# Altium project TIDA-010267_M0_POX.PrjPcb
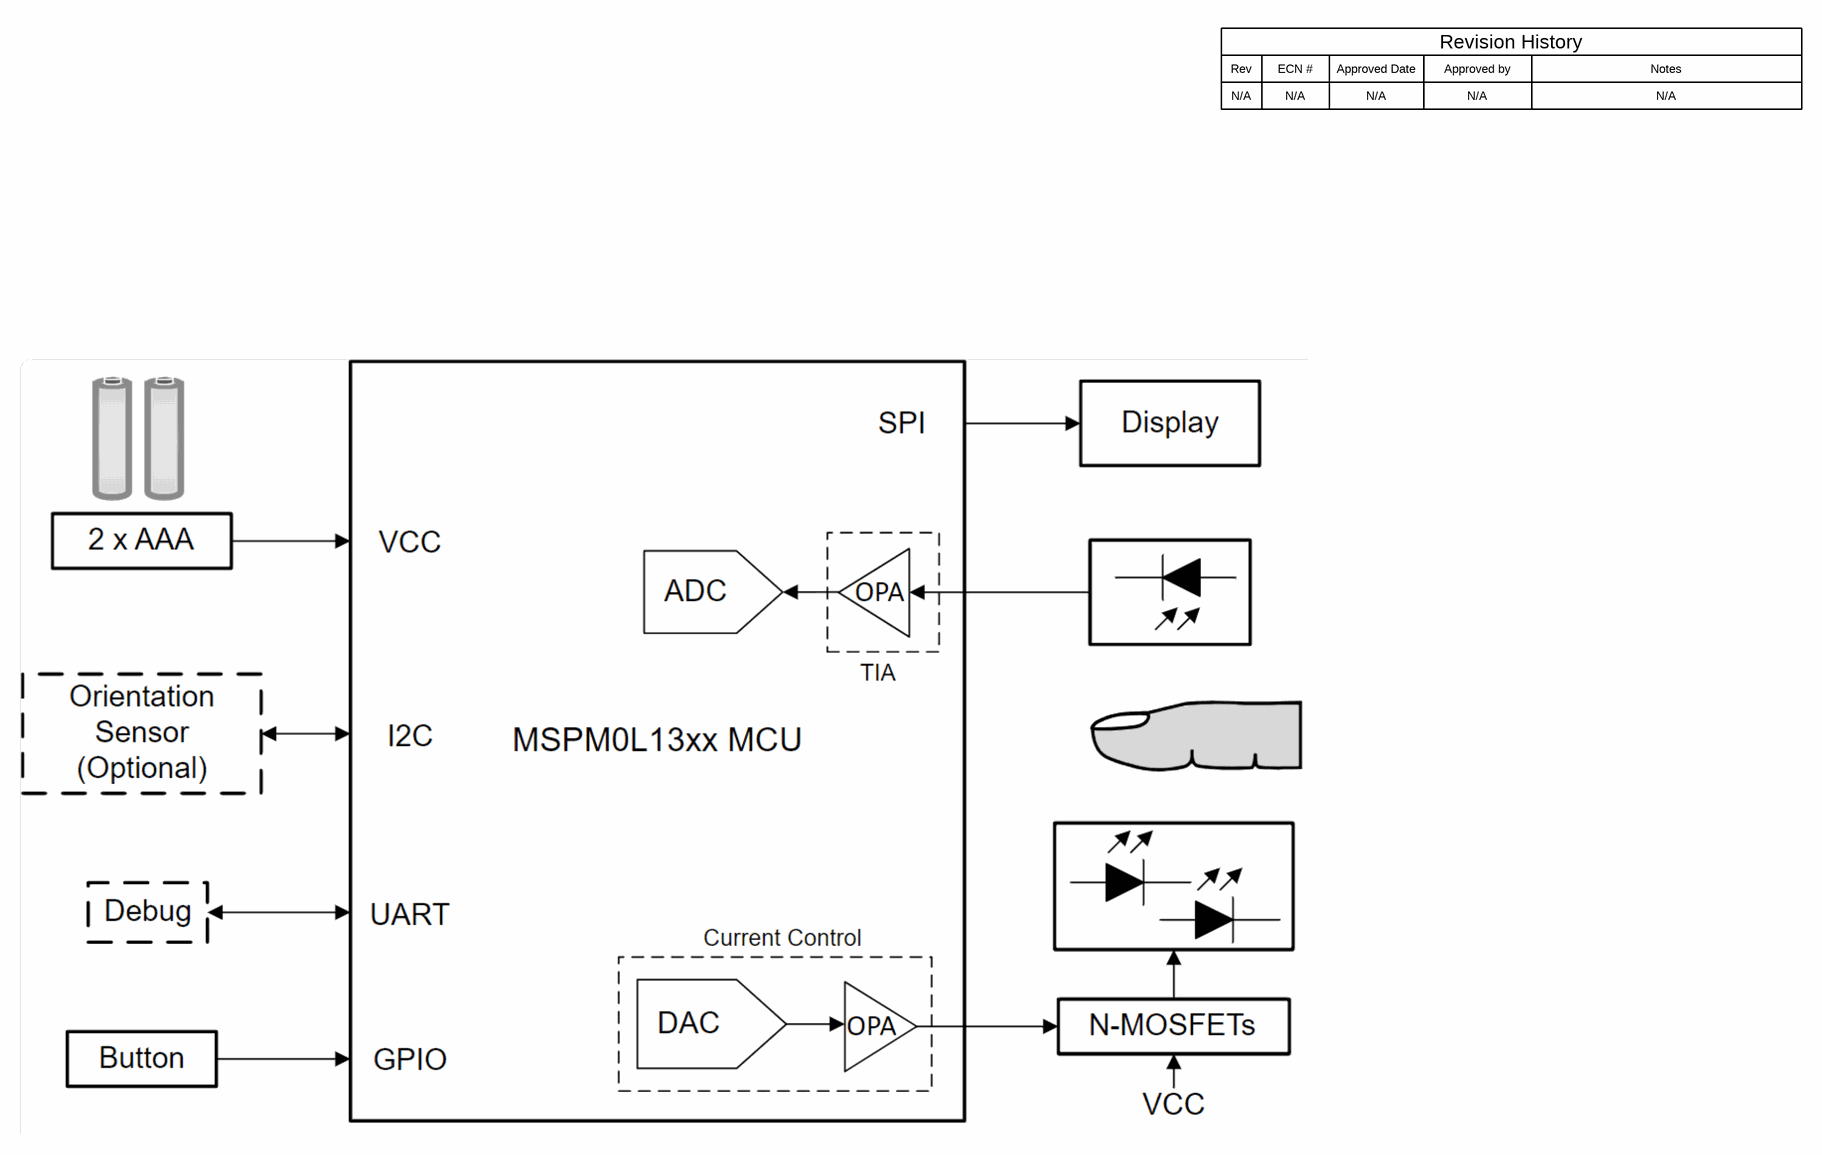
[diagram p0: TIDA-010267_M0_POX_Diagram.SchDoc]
TID: N/A; TechSupport: http://www.ti.com/support; SCH_Rev: A; PRJ_Title: TIDA-010267_M0_POX; PRJ_Number: TIDA-010267_M0_POX; PRJ_Engineer: Rogelio Armino; PRJ_Customer: Public Release; PCB_Rev: A; PCB_Layout: Rogelio Armino; CopyrightYear: 2023
3 sheets, 43 parts. Net scope: global (net labels, ports and power ports of the same name join across sheets).
Board file: TIDA-010267_M0_POX_PCB.PcbDoc
Sheets:
  TIDA-010267_M0_POX_Diagram.SchDoc
  TIDA-010267_M0_POX_Schematic.SchDoc
  TIDA-010267_M0_POX_Hardware.SchDoc

## Sheet TIDA-010267_M0_POX_Diagram.SchDoc
size 431 x 279 mm; Date: Not shown in title block; ApprovedBy: Not shown in title block; CheckedBy: Not shown in title block; Author: Not shown in title block; CompanyName: Not shown in title block; Engineer: Not shown in title block; Organization: Not shown in title block; Address1: Not shown in title block; Address2: Not shown in title block; Address3: Not shown in title block; Address4: Not shown in title block; DocumentNumber: 1; Revision: Use project parameter SCH_Rev; SheetNumber: 1; SheetTotal: 3; PageSetup: Record=PageOptions¦CenterHorizontal=True¦CenterVertical=True¦PrintScale=1.00¦XCorrection=1.00¦YCorrection=1.00¦PrintKind=0¦BorderSize=5000000¦LeftOffset=0¦BottomOffset=0¦Orientation=2¦PaperLength=1000¦PaperWidth=1000¦Scale=100¦PaperSource=15¦PrintQuality=600¦MediaType=1¦DitherType=10¦PaperKind=Letter¦PrintScaleMode=1

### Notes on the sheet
- Rev
- N/A
- ECN #
- Approved Date
- Approved by
- Revision History
- Notes

## Sheet TIDA-010267_M0_POX_Schematic.SchDoc
size 431 x 279 mm; Date: Not shown in title block; ApprovedBy: Not shown in title block; CheckedBy: Not shown in title block; Author: Not shown in title block; CompanyName: Not shown in title block; Engineer: Not shown in title block; Organization: Not shown in title block; Address1: Not shown in title block; Address2: Not shown in title block; Address3: Not shown in title block; Address4: Not shown in title block; DocumentNumber: 2; Revision: Use project parameter SCH_Rev; SheetNumber: 2; SheetTotal: 3; PageSetup: Record=PageOptions¦CenterHorizontal=True¦CenterVertical=True¦PrintScale=1.00¦XCorrection=1.00¦YCorrection=1.00¦PrintKind=0¦BorderSize=5000000¦LeftOffset=0¦BottomOffset=0¦Orientation=2¦PaperLength=1000¦PaperWidth=1000¦Scale=100¦PaperSource=15¦PrintQuality=600¦MediaType=1¦DitherType=10¦PaperKind=Letter¦PrintScaleMode=1
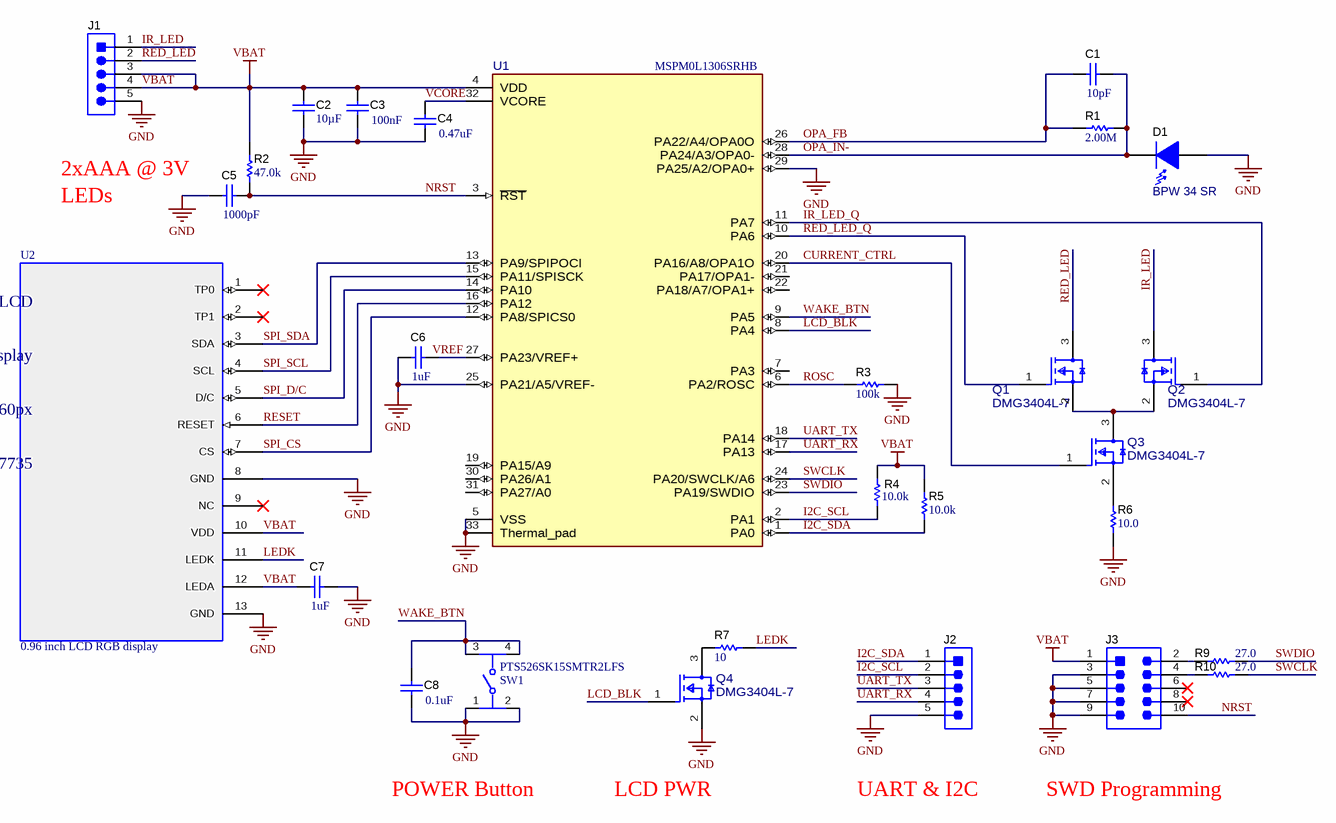
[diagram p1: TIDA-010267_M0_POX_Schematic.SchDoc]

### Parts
C1  ValueDisplayed: 10pF  [0402]  (hidden comment: C0402C100C8GACTU)
C2  ValueDisplayed: 10µF  [0603]  (hidden comment: GRM188R61A106KAALD)
C3  ValueDisplayed: 100nF  [0402]  (hidden comment: GRM155R61A104KA01D)
C4  ValueDisplayed: 0.47uF  [0402]  (hidden comment: GRM155R61A474KE15D)
C5  ValueDisplayed: 1000pF  [0402]  (hidden comment: GRM155R61A102KA01D)
C6  ValueDisplayed: 1uF  [0402]  (hidden comment: GRM155R61E105KA12D)
C7  ValueDisplayed: 1uF  [0402]  (hidden comment: GRM155R61E105KA12D)
C8  ValueDisplayed: 0.1uF  [0402L]  (hidden comment: GRM155R61A104KA01D)
D1  BPW 34 SR  [BPW34SR]
J1  61300511121  [Wurth_61300511121]  (value not drawn)
J2  61300511121  [Wurth_61300511121]  (value not drawn)
J3  FTSH-105-01-L-DV-K  [Samtec_FTSH-105-01-x-DV-K]  (value not drawn)
Q1  DMG3404L-7  [FP-DMG3404L-7_SOT23-MFG]
Q2  DMG3404L-7  [FP-DMG3404L-7_SOT23-MFG]
Q3  DMG3404L-7  [FP-DMG3404L-7_SOT23-MFG]
Q4  DMG3404L-7  [FP-DMG3404L-7_SOT23-MFG]
R1  ValueDisplayed: 2.00M  [0402]  (hidden comment: CRCW04022M00FKED)
R2  ValueDisplayed: 47.0k  [0402]  (hidden comment: RC0402FR-0747KL)
R3  ValueDisplayed: 100k  [0402]  (hidden comment: RG1005P-104-B-T5)
R4  ValueDisplayed: 10.0k  [0402]  (hidden comment: ERJ-2RKF1002X)
R5  ValueDisplayed: 10.0k  [0402]  (hidden comment: ERJ-2RKF1002X)
R6  ValueDisplayed: 10.0  [0603]  (hidden comment: RC0603FR-0710RL)
R7  ValueDisplayed: 10  [0402L]  (hidden comment: CRCW040210R0JNED)
R9  ValueDisplayed: 27.0  [CPF0402]  (hidden comment: CPF0402B27RE1)
R10  ValueDisplayed: 27.0  [CPF0402]  (hidden comment: CPF0402B27RE1)
SW1  PTS526SK15SMTR2LFS  [FP-PTS526SK15SMTR2LFS-MFG]
U1  MSPM0L1306SRHB  [RHB0032N-MFG]
U2  0.96 inch LCD RGB display  [MDT0096A2IS-SPI]

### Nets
GND: C2.2 C3.2 C4.2 C5.2 C6.2 C7.1 C8.2 D1.1(A) J1.5 J2.5 J3.3 J3.5 J3.7 J3.9 Q4.2(S) R3.2 R6.1 SW1.1 SW1.2 U1.5(VSS) U1.25(PA21/A5/VREF-) U1.29(PA25/A2/OPA0+) U1.33(Thermal_pad) U2.8(GND) U2.13(GND)
VBAT: C2.1 C3.1 C7.2 J1.3 J1.4 J3.1 R2.2 R4.2 R5.2 U1.4(VDD) U2.10(VDD) U2.12(LEDA)
CURRENT_CTRL: Q3.1(G) U1.20(PA16/A8/OPA1O)
I2C_SCL: J2.2 R4.1 U1.2(PA1)
I2C_SDA: J2.1 R5.1 U1.1(PA0)
IR_LED: J1.1 Q2.3(D)
IR_LED_Q: Q2.1(G) U1.11(PA7)
LCD_BLK: Q4.1(G) U1.8(PA4)
LEDK: R7.2 U2.11(LEDK)
NRST: C5.1 J3.10 R2.1 U1.3(~{RST})
OPA_FB: C1.2 R1.1 U1.26(PA22/A4/OPA0O)
OPA_IN-: C1.1 D1.2(C) R1.2 U1.28(PA24/A3/OPA0-)
RED_LED: J1.2 Q1.3(D)
RED_LED_Q: Q1.1(G) U1.10(PA6)
RESET: U1.16(PA12) U2.6(RESET)
ROSC: R3.1 U1.6(PA2/ROSC)
SPI_CS: U1.12(PA8/SPICS0) U2.7(CS)
SPI_D/C: U1.14(PA10) U2.5(D/C)
SPI_SCL: U1.15(PA11/SPISCK) U2.4(SCL)
SPI_SDA: U1.13(PA9/SPIPOCI) U2.3(SDA)
SWCLK: R10.2 U1.24(PA20/SWCLK/A6)
SWDIO: R9.2 U1.23(PA19/SWDIO)
UART_RX: J2.4 U1.17(PA13)
UART_TX: J2.3 U1.18(PA14)
VCORE: C4.1 U1.32(VCORE)
WAKE_BTN: C8.1 SW1.3 SW1.4 U1.9(PA5)
NetC6_1: C6.1 U1.27(PA23/VREF+)
NetJ3_2: J3.2 R9.1
NetJ3_4: J3.4 R10.1
NetQ1_2: Q1.2(S) Q2.2(S) Q3.3(D)
NetQ3_2: Q3.2(S) R6.2
NetQ4_3: Q4.3(D) R7.1

Not connected (* = marked no-connect by the designer): J3 6* 8*; U1 7(PA3) 19(PA15/A9) 21(PA17/OPA1-) 22(PA18/A7/OPA1+) 30(PA26/A1) 31(PA27/A0); U2 1(TP0)* 2(TP1)* 9(NC)*

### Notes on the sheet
- 2xAAA @ 3V
- LEDs
- POWER Button
- LCD PWR
- UART & I2C
- SWD Programming
- Labels drawn without touching a wire or pin: VREF

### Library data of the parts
C1 = CMP-0064914-2: CAP, CERM, 10 pF, 10 V,+/- 2.5%, C0G/NP0, 0402; Manufacturer: Kemet; TaMin_C: -55°C; Polarized: N; SizeAreaWB_mm2: 3; Value1: Unknown; U/M: EA; Value: 10pF; TaMax_C: 125°C; SizeZ_mm: 0.6; SizeX_mm: 1; SizeY_mm: 0.5; Value2: 10V; AEC Category: Q200
C2 = CMP-0086193-1: CAP, CERM, 10 µF, 10 V,+/- 10%, X5R, 0603; Manufacturer: MuRata; SizeArea_mm2: 1.28; SizeY_mm: 0.8; TaMax_C: 85°C; TaMin_C: -55°C; Polarized: N; Value2: 10V; SizeAreaWB_mm2: 4.68; SizeZ_mm: 1; SizeX_mm: 1.6; AEC Category: Q200; U/M: EA; Value: 10uF
C3 = CMP-0006562-2: CAP, CERM, 0.1 uF, 10 V, +/- 10%, X5R, 0402; Manufacturer: MuRata; TaMin_C: -55°C; Polarized: N; SizeAreaWB_mm2: 3; Value1: Unknown; U/M: EA; Value: 0.1uF; TaMax_C: 85°C; SizeZ_mm: 0.6; SizeX_mm: 1; SizeY_mm: 0.5; Value2: 10V; AEC Category: Q200
C4 = CMP-0006580-2: CAP, CERM, 0.47 uF, 10 V, +/- 10%, X5R, 0402; Manufacturer: MuRata; TaMin_C: -55°C; Polarized: N; SizeAreaWB_mm2: 3; Value1: Unknown; U/M: EA; Value: 0.47uF; TaMax_C: 85°C; SizeZ_mm: 0.6; SizeX_mm: 1; SizeY_mm: 0.5; Value2: 10V; Cap_F: 470nF; AEC Category: Q200
C5 = CMP-0006560-2: CAP, CERM, 1000 pF, 10 V, +/- 10%, X5R, 0402; Manufacturer: MuRata; TaMin_C: -55°C; Polarized: N; SizeAreaWB_mm2: 3; Value1: Unknown; U/M: EA; Value: 1000pF; TaMax_C: 85°C; SizeZ_mm: 0.6; SizeX_mm: 1; SizeY_mm: 0.5; Value2: 10V; Cap_F: 1nF; AEC Category: Q200
C6 C7 = CMP-0006608-2: CAP, CERM, 1 uF, 25 V, +/- 10%, X5R, 0402; Manufacturer: MuRata; TaMin_C: -55°C; Polarized: N; SizeAreaWB_mm2: 3; Value1: Unknown; U/M: EA; Value: 1uF; TaMax_C: 85°C; SizeZ_mm: 0.6; SizeX_mm: 1; SizeY_mm: 0.5; Value2: 25V; Cap_F: 1µF; AEC Category: Q200
C8 = CMP-0006562-2: CAP, CERM, 0.1 uF, 10 V, +/- 10%, X5R, 0402; Manufacturer: MuRata; TaMin_C: -55°C; Polarized: N; SizeAreaWB_mm2: 3; Value1: Unknown; U/M: EA; Value: 0.1uF; TaMax_C: 85°C; SizeZ_mm: 0.6; SizeX_mm: 1; SizeY_mm: 0.5; Cap_Case: 0402; Value2: 10V; Cap_F: 100nF; AEC Category: Q200
D1 = CMP-0005335-2: PIN Photodiode, SMD; Manufacturer: OSRAM
J1 J2 = CMP-0084909-1: Header, 2.54mm, 5x1, Gold, TH; Manufacturer: Wurth Elektronik; Pitch_mm: 2.54; Gender: Male; Row_Count: 1; Shrouded: N; Current_A: 3A; Voltage_V: 250V
J3 = CMP-0075634-2: Header(Shrouded), 1.27mm, 5x2, Gold, SMT; Manufacturer: Samtec; Pitch_mm: 1.27; Gender: Male; Cert_CSA: Y; Current_A: 3.3A; Row_Count: 2
Q1-Q4 = CMP-0001689-1: MOSFET N-Channel 30 V 4.2A (Ta) 780mW (Ta) Surface Mount SOT-23-3; Manufacturer: Diodes Inc.; AEC Qualified: No; QgTyp_nC: 13.2nC @ 10V; Rdson45_ohm: 21m; SizeZ_mm: 1.1mm; VdsMax_V: 1V; Vgs_V: 20V; ChMode: False; Drain To Source Breakdown Voltage: 30V; Input Capacitace At Vds: 641pF @ 15V; Number Of Channels: 1; Power_W: 0.78W; Pulse Drain Current: 30A; Rthja Max: 164°C/W; Standoff Height: 0.013mm; Threshold Vgs Max: 2V; TJmax_C: +150°C; Turn Off Delay Time: 22ns; Turn On Delay Time: 3.3ns; Typ Forward Diode Voltage: 0.75V
R1 = CMP-0026245-2: RES, 2.00 M, 1%, 0.063 W, AEC-Q200 Grade 0, 0402; Manufacturer: Vishay-Dale; Power_W: 63mW; TempCo: 100 ppm/C; Value_Code: 2M00; Value: 2.00Meg; EIA_Code: E96; Res_ohm: 2M; SizeX_mm: 1; SizeY_mm: 0.5; SizeZ_mm: 0.6; Value2: 0.063W; AEC Qualified: Y; VDC_V: 50V; AEC Category: Q200; AEC Grade: 0
R2 = CMP-0026737-1: RES, 47.0 k, 1%, 0.0625 W, 0402; Manufacturer: Yageo America; Power_W: 62.5mW; TempCo: 100 ppm/C; Value_Code: 47k0; U/M: EA; Value: 47.0k; Res_ohm: 47k; SizeX_mm: 1; SizeY_mm: 0.5; SizeZ_mm: 0.6; AEC Qualified: N; VDC_V: 50V; AEC Category: Q200
R3 = CMP-0026815-1: RES, 100 k, 0.1%, 0.063 W, 0402; Manufacturer: Susumu Co Ltd; Power_W: 63mW; TempCo: 25 ppm/C; U/M: EA; Value: 100k; EIA_Code: E192; SizeX_mm: 1; SizeY_mm: 0.5; SizeZ_mm: 0.6; Value2: 0.063W; AEC Category: Q200
R4 R5 = CMP-0026658-1: RES, 10.0 k, 1%, 0.1 W, 0402; Manufacturer: Panasonic; Power_W: 100mW; TempCo: 100 ppm/C; Value_Code: 10k0; U/M: EA; Value: 10.0k; EIA_Code: E96; Res_ohm: 10k; SizeX_mm: 1; SizeY_mm: 0.5; SizeZ_mm: 0.6; Value2: 0.1W; VDC_V: 50V; AEC Category: Q200
R6 = CMP-0022751-4: RES, 10.0, 1%, 0.1 W, 0603; Manufacturer: Yageo; Power_W: 100mW; TempCo: 100 ppm/C; Value_Code: 10R0; Value: 10.0; EIA_Code: E96; Res_ohm: 10; SizeX_mm: 1.6; SizeY_mm: 0.8; SizeZ_mm: 1; Value2: 0.1W; SizeArea_mm2: 1.28; AEC Qualified: N; VDC_V: 75V; AEC Category: Q200; SizeAreaWB_mm2: 4.68
R7 = CMP-0026827-3: RES, 10, 5%, 0.063 W, AEC-Q200 Grade 0, 0402; Manufacturer: Vishay-Dale; Power_W: 63mW; TempCo: 200 ppm/C; Value_Code: 10R0; Value: 10; EIA_Code: E24; SizeX_mm: 1; SizeY_mm: 0.5; SizeZ_mm: 0.6; Value2: 0.063W; AEC Qualified: Y; VDC_V: 50V; AEC Category: Q200; AEC Grade: 0
R9 R10 = CMP-0026767-1: RES, 27, 0.1%, 0.063 W, 0402; Manufacturer: TE Connectivity; Power_W: 63mW; TempCo: 25 ppm/C; Value_Code: 27R0; U/M: EA; Value: 27; SizeX_mm: 1; SizeY_mm: 0.5; SizeZ_mm: 0.35; Value2: 0.063W; AEC Qualified: N; AEC Category: Q200
SW1 = CMP-10040-000013-1: TACT 5.2 X 5.2, 1.5 MM H, 260GF,; Manufacturer: C&K; Operating Force: 250gf; Throw Configuration: SPST-NO; Contact Current Rating: 50mA; Standoff Height: 0mm; Contact Resistance: 100mΩ; Voltage Rating Dc: 12V; Electromechanical Life: 200000Cycles
U1 = CMP-0093968-1: MSPM0L130x Mixed-Signal Microcontrollers; Manufacturer: Texas Instruments; Number Of Pwm Channels: 8; TJmax_C: +130°C; Interface: I2C,SPI,UART,LIN,IrDA,SMBus; Number Of I2C Channels: 2; Memory Size: 64KBytes; Core Architecture: ARM Cortex-M0+; Number Of Spi Channels: 1; Min Supply Voltage: 1.62V; Ram Size: 4KBytes; Data Bus Width: 32bits; TaMax_C: +125°C; Frequency_Fixed: 32MHz; Memory Type: FLASH; Number Of Adc Channels: 10; Standoff Height: 0mm; AEC Qualified: No; Number Of I/Os: 28; TaMin_C: -40°C; SizeZ_mm: 1mm; Max Supply Voltage: 3.6V; Number Of Timers/Counters: 4
U2 = GMT096-01

## Sheet TIDA-010267_M0_POX_Hardware.SchDoc
size 431 x 279 mm; Date: Not shown in title block; ApprovedBy: Not shown in title block; CheckedBy: Not shown in title block; Author: Not shown in title block; CompanyName: Not shown in title block; Engineer: Not shown in title block; Organization: Not shown in title block; Address1: Not shown in title block; Address2: Not shown in title block; Address3: Not shown in title block; Address4: Not shown in title block; DocumentNumber: 3; Revision: Use project parameter SCH_Rev; SheetNumber: 3; SheetTotal: 3; PageSetup: Record=PageOptions¦CenterHorizontal=True¦CenterVertical=True¦PrintScale=1.00¦XCorrection=1.00¦YCorrection=1.00¦PrintKind=0¦BorderSize=5000000¦LeftOffset=0¦BottomOffset=0¦Orientation=2¦PaperLength=1000¦PaperWidth=1000¦Scale=100¦PaperSource=15¦PrintQuality=600¦MediaType=1¦DitherType=10¦PaperKind=Letter¦PrintScaleMode=1
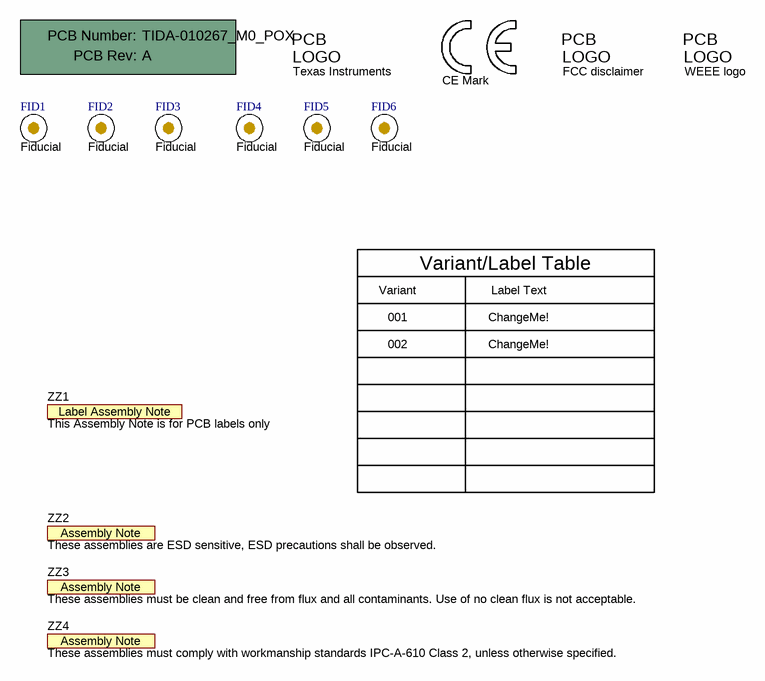
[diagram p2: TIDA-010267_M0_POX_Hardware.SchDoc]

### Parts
!PCB1  Printed Circuit Board  (value not drawn)  (mechanical)
FID1  Fiducial  [Fiducial10-30]
FID2  Fiducial  [Fiducial10-30]
FID3  Fiducial  [Fiducial10-30]
FID4  Fiducial  [Fiducial10-30]
FID5  Fiducial  [Fiducial10-30]
FID6  Fiducial  [Fiducial10-30]
Logo1  CE Mark  [CE_Mark_5mm]  (no BOM)
Logo2  Texas Instruments  [TI_Symbol_Overlay_Small]  (no BOM)
Logo3  FCC disclaimer  [FCC_disclaimer]  (no BOM)
Logo4  WEEE logo  [WEEE_Minimum]  (no BOM)
ZZ1  This Assembly Note is for PCB labels only  [AssemblyNoteLabel]  (no BOM)
ZZ2  These assemblies are ESD sensitive, ESD precautions shall be observed.  [AssemblyNote]  (no BOM)
ZZ3  These assemblies must be clean and free from flux and all contaminants. Use of no clean flux is not acceptable.  [AssemblyNote]  (no BOM)
ZZ4  These assemblies must comply with workmanship standards IPC-A-610 Class 2, unless otherwise specified.  [AssemblyNote]  (no BOM)

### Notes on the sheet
- Variant
- Variant/Label Table
- Label Text
- 001
- 002
- ChangeMe!

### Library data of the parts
!PCB1 = CMP-0003618-2: Manufacturer: Any; PartNumber: TIDA-010267_M0_POX
FID1-FID6 = CMP-0077181-1: Fiducial mark.  There is nothing to buy or mount.
Logo1 = CMP-0074844-1: SymbolCreator: a0412235
Logo2 = CMP-0074838-1: Texas Instrument Corporate Signature; SymbolCreator: a0412235; Lib Reference: TI_Logo; Library Reference: Logo
Logo3 = CMP-0074847-1: FCC_disclaimer; Library Reference: Logo
Logo4 = CMP-0074769-1
ZZ1 = CMP-0003616-3
ZZ2 = CMP-0077236-1
ZZ3 = CMP-0077237-1
ZZ4 = CMP-0077238-1

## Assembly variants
001: not fitted C8 FID1 FID2 FID3 J1 J2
